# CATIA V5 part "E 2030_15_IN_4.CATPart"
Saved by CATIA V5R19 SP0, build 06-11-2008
Material "Plastic": density 1200 kg/m3, Young's modulus 2.2e+09 Pa, Poisson ratio 0.38, thermal expansion 6.84e-05 1/K
Bounding box of the stored display mesh (mm): x 60.4 to 75.5, y -7.54 to 7.54, z -2 to 0
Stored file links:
  G:\UTB\Kombinované\Bakalářská práce\Catia\FORMA\E 2030_15_IN_4.CATPart
  D:\Aplikace\CATIA\Nová složka\win_b64\startup\materials\Catalog.CATMaterial
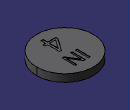
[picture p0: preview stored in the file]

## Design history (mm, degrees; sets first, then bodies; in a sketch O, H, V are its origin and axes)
Body1 "E 2030_15_IN_1-8" (main body)
  Solid1: solid without history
